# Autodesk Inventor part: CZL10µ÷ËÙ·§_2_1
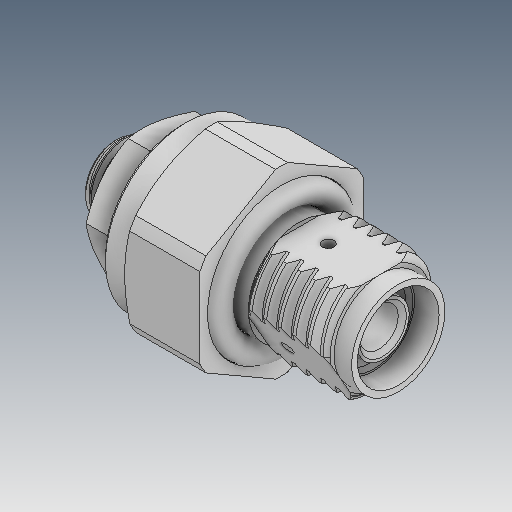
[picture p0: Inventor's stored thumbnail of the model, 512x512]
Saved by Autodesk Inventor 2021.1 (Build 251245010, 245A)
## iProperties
Created: 2019-04
Part Number: CZL10µ÷ËÙ·§_2_1
Material: Ogólny
Document SubType Name: Modeling
Designer: user
Density: 1 g/cm^3
Appearance: Domyślna
Author: user
Revision Number: ÈÎºÎ
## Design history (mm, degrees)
feature "ÊäÈë2"
feature "ÊäÈë3"
feature "ÊäÈë5"
node "Bryła1"
node "Bryła2"
node "Bryła3"
